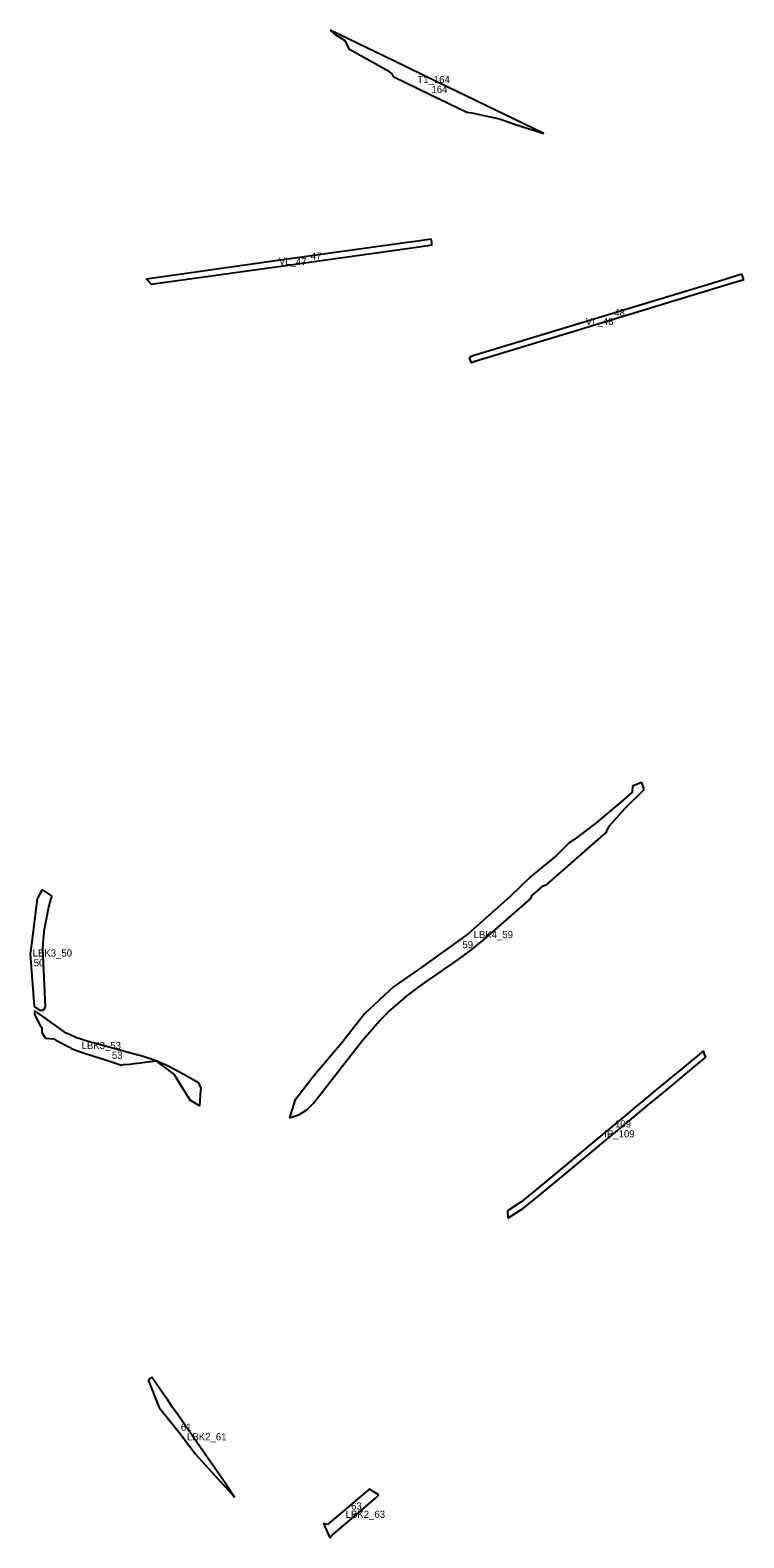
# Model space of a CAD drawing. Extents: x -521939 to -518034, y -1194984 to -1189555.
# Drawn here: x -519031 to -518034, y -1194984 to -1192880 of the extents above; entities that cross this region are included whole.
import ezdxf

# ---------------------------------------------------------------- set-up
doc = ezdxf.new("R2010")
doc.units = 0
for name, color, linetype in [('96120023', 7, 'Continuous'), ('96140023', 7, 'Continuous'), ('ID VPO', 7, 'Continuous'), ('ID VPS', 7, 'Continuous')]:
    doc.layers.add(name, color=color, linetype=linetype)

msp = doc.modelspace()

# ---------------------------------------------------------------- linework, layer by layer
at = {"layer": '96120023'}
for points in [[(-518313.58, -1193023.8), (-518462.75, -1192951.72), (-518523.11, -1192922.54), (-518611.93, -1192879.62), (-518611.95, -1192879.61)], [(-518611.95, -1192879.61), (-518604.74, -1192885.62)], [(-518604.74, -1192885.62), (-518591.47, -1192894.23)], [(-518591.47, -1192894.23), (-518586.01, -1192905.56), (-518533.4, -1192935.15)], [(-518533.4, -1192935.15), (-518525.77, -1192940.63), (-518522.92, -1192944.85)], [(-518522.92, -1192944.85), (-518472.09, -1192969.41)], [(-518472.09, -1192969.41), (-518421.27, -1192993.97)], [(-518421.27, -1192993.97), (-518421.26, -1192993.97)], [(-518421.26, -1192993.97), (-518414.09, -1192994.92), (-518388.43, -1193000.81), (-518375.31, -1193003.18), (-518354.48, -1193010.65)], [(-518354.48, -1193010.65), (-518345.74, -1193013.45)], [(-518345.74, -1193013.45), (-518332.79, -1193017.61), (-518313.58, -1193023.8)], [(-518471.02, -1193171.35), (-518489.33, -1193173.91)], [(-518469.31, -1193179.19), (-518471.02, -1193171.35)], [(-518489.33, -1193173.91), (-518507.69, -1193176.48), (-518688.29, -1193201.76), (-518868.39, -1193226.97), (-518861.71, -1193234.11), (-518680.88, -1193208.8), (-518488.19, -1193181.83)], [(-518488.19, -1193181.83), (-518469.31, -1193179.19)], [(-518037.03, -1193220.36), (-518069.91, -1193230.34), (-518241.69, -1193282.48), (-518414.03, -1193334.79)], [(-518411.17, -1193342.06), (-518236.07, -1193288.88), (-518060.97, -1193235.7), (-518034.3, -1193227.6)], [(-518034.3, -1193227.6), (-518037.03, -1193220.36)], [(-518414.03, -1193334.79), (-518417.99, -1193336.8)], [(-518417.99, -1193336.8), (-518415.16, -1193344.07)], [(-518415.16, -1193344.07), (-518411.17, -1193342.06)], [(-518090.78, -1194303.93), (-518120.84, -1194329.01)], [(-518087.28, -1194312.72), (-518089.43, -1194308.57), (-518090.78, -1194303.93)], [(-518120.84, -1194329.01), (-518156.04, -1194358.17)], [(-518152.05, -1194366.76), (-518087.28, -1194312.72)], [(-518173.76, -1194372.91), (-518185.81, -1194382.9)], [(-518156.04, -1194358.17), (-518173.76, -1194372.91)], [(-518168.73, -1194380.59), (-518153.38, -1194367.87), (-518152.05, -1194366.76)], [(-518185.81, -1194382.9), (-518199.57, -1194394.33)], [(-518185.85, -1194394.67), (-518168.73, -1194380.59)], [(-518274.04, -1194467.87), (-518229.68, -1194431.04), (-518207.82, -1194412.86), (-518185.85, -1194394.67)], [(-518199.57, -1194394.33), (-518245.06, -1194432.12)], [(-518245.06, -1194432.12), (-518304.03, -1194481.14)], [(-518293.63, -1194484.18), (-518274.04, -1194467.87)], [(-518317.05, -1194491.98), (-518340.81, -1194511.5)], [(-518319.41, -1194505.51), (-518293.63, -1194484.18)], [(-518304.03, -1194481.14), (-518317.05, -1194491.98)], [(-518340.81, -1194511.5), (-518345.29, -1194514.98), (-518364.14, -1194527.29)], [(-518363.86, -1194537.39), (-518341.98, -1194523.73), (-518319.41, -1194505.51)], [(-518364.14, -1194527.29), (-518363.86, -1194537.39)]]:
    msp.add_lwpolyline(points, dxfattribs=at)
at = {"layer": '96140023'}
for points in [[(-518176.81, -1193929.72), (-518179.54, -1193930.3), (-518189.98, -1193934.67)], [(-518173.64, -1193939.33), (-518176.81, -1193929.72)], [(-518225.95, -1193998.27), (-518222.25, -1193990.41), (-518200, -1193965.24), (-518173.64, -1193939.33)], [(-518190.04, -1193942.98), (-518205.7, -1193956.46)], [(-518189.98, -1193934.67), (-518190.04, -1193942.98)], [(-518205.7, -1193956.46), (-518240.91, -1193986.11)], [(-518240.91, -1193986.11), (-518271.56, -1194009.45), (-518278.37, -1194013.9)], [(-518655.68, -1194393.54), (-518644.23, -1194386.38), (-518634.76, -1194376.7), (-518566.27, -1194288.86), (-518542.85, -1194262.27), (-518530.28, -1194249.78), (-518503.56, -1194226.5), (-518482.17, -1194210.72), (-518433.41, -1194176.9), (-518415.71, -1194163.89), (-518398.75, -1194149.91), (-518332.7, -1194092.34), (-518329.88, -1194087.32), (-518314.52, -1194073.94), (-518309.55, -1194072.16), (-518226.78, -1194000.03)], [(-518278.37, -1194013.9), (-518296.03, -1194031.57), (-518332.33, -1194061.21)], [(-518226.78, -1194000.03), (-518225.95, -1193998.27)], [(-518332.33, -1194061.21), (-518361.02, -1194088.99), (-518419.1, -1194140.67), (-518483.93, -1194187.46), (-518523.23, -1194214.71)], [(-519020.73, -1194091.88), (-519024.61, -1194121.8), (-519028.49, -1194151.72), (-519029.89, -1194162.52), (-519030.29, -1194165.62), (-519030.69, -1194168.71), (-519027.95, -1194205.37), (-519025.2, -1194242.02)], [(-519013.71, -1194079.07), (-519020.73, -1194091.88)], [(-518999.95, -1194088.17), (-519013.71, -1194079.07)], [(-519004.84, -1194105.44), (-519001.62, -1194092.79), (-518999.95, -1194088.17)], [(-519012.79, -1194161.44), (-519012.2, -1194148.13), (-519010.43, -1194134.4), (-519004.84, -1194105.44)], [(-519012.22, -1194247.18), (-519009.11, -1194242.54), (-519012.79, -1194161.44)], [(-518523.23, -1194214.71), (-518563.39, -1194252.1)], [(-519025.2, -1194242.02), (-519017.78, -1194247.27)], [(-518793.68, -1194380.64), (-518792.24, -1194359.26), (-518791.99, -1194355.76), (-518795.83, -1194348.62), (-518799.64, -1194346.49), (-518816.36, -1194337.16), (-518838.06, -1194325.4), (-518851.56, -1194319.21), (-518862.69, -1194315.05), (-518865.77, -1194314.1), (-518872.91, -1194311.92), (-518892.05, -1194306.64), (-518905.25, -1194303.03), (-518910.54, -1194301.58), (-518937.1, -1194294.31), (-518946.44, -1194291.75), (-518954.36, -1194289.64), (-518962.17, -1194287.03), (-518966.08, -1194285.71), (-518975.52, -1194281.45), (-518980.26, -1194279.31), (-518993.95, -1194269.72), (-519001.41, -1194264.41), (-519008.87, -1194259.09), (-519017.53, -1194252.96), (-519023.94, -1194248.41), (-519024.71, -1194250.04), (-519024.49, -1194253.08)], [(-519024.49, -1194253.08), (-519017.06, -1194268.42)], [(-519017.78, -1194247.27), (-519012.22, -1194247.18)], [(-518563.39, -1194252.1), (-518595.65, -1194293.01), (-518634.33, -1194338.71), (-518661.16, -1194373.51)], [(-519017.06, -1194268.42), (-519014.59, -1194271.5)], [(-519014.59, -1194271.5), (-519014.52, -1194278.4), (-519009.2, -1194286.28)], [(-519009.2, -1194286.28), (-518997.55, -1194287.28), (-518994.7, -1194289.4), (-518975.86, -1194299.17)], [(-518975.86, -1194299.17), (-518972.84, -1194300.73)], [(-518972.84, -1194300.73), (-518969.65, -1194302.39), (-518959.1, -1194305.82)], [(-518959.1, -1194305.82), (-518939.19, -1194312.3)], [(-518939.19, -1194312.3), (-518928.2, -1194315.87)], [(-518928.2, -1194315.87), (-518903.28, -1194323.98)], [(-518903.28, -1194323.98), (-518901.43, -1194323.75)], [(-518901.43, -1194323.75), (-518900.67, -1194323.31), (-518891.75, -1194322.51), (-518855.36, -1194317.86)], [(-518855.36, -1194317.86), (-518829.53, -1194336.97)], [(-518829.53, -1194336.97), (-518816.88, -1194357.57), (-518807.62, -1194372.64)], [(-518807.62, -1194372.64), (-518794.51, -1194380.48)], [(-518794.51, -1194380.48), (-518793.68, -1194380.64)], [(-518661.16, -1194373.51), (-518668.49, -1194397.81)], [(-518668.49, -1194397.81), (-518655.68, -1194393.54)], [(-518860.9, -1194759.36), (-518865.86, -1194763.22)], [(-518865.86, -1194763.22), (-518855.5, -1194789.32)], [(-518845.5, -1194781.65), (-518860.9, -1194759.36)], [(-518855.5, -1194789.32), (-518850.84, -1194801.06)], [(-518838.55, -1194791.71), (-518845.5, -1194781.65)], [(-518831.36, -1194802.11), (-518838.55, -1194791.71)], [(-518850.84, -1194801.06), (-518850.19, -1194802.69)], [(-518850.19, -1194802.69), (-518843.34, -1194811.13)], [(-518843.34, -1194811.13), (-518835.53, -1194820.44)], [(-518824.2, -1194812.48), (-518831.36, -1194802.11)], [(-518745.52, -1194926.78), (-518758.18, -1194908.03), (-518809.54, -1194833.7), (-518824.2, -1194812.48)], [(-518835.53, -1194820.44), (-518820.29, -1194839.32)], [(-518820.29, -1194839.32), (-518800.02, -1194866.93), (-518745.52, -1194926.78)], [(-518561.44, -1194919.5), (-518588.48, -1194942.32), (-518615.53, -1194965.15)], [(-518557.27, -1194915.81), (-518559.35, -1194917.65), (-518561.44, -1194919.5)], [(-518543.87, -1194923.75), (-518557.27, -1194915.81)], [(-518578.49, -1194954.01), (-518547.93, -1194927.89)], [(-518547.93, -1194927.89), (-518543.87, -1194923.75)], [(-518609.05, -1194980.13), (-518578.49, -1194954.01)], [(-518615.53, -1194965.15), (-518621.14, -1194963.55)], [(-518621.14, -1194963.55), (-518612.46, -1194983.75)], [(-518612.46, -1194983.75), (-518609.05, -1194980.13)]]:
    msp.add_lwpolyline(points, dxfattribs=at)

# ---------------------------------------------------------------- texts
at = {"layer": '96120023'}
for s, rotation, p in [('T1_164', 0, (-518490.18, -1192953.48)), ('VL_47', 0, (-518683.34, -1193207.28)), ('VL_48', 360, (-518255.01, -1193291.13)), ('IP_109', 360, (-518229.22, -1194424.87))]:
    msp.add_text(s, height=10, rotation=rotation, dxfattribs=at).set_placement(p)
at = {"layer": '96140023'}
for s, rotation, p in [('LBK4_59', 0, (-518411.62, -1194146.8)), ('LBK3_50', 0, (-519027.22, -1194172.56)), ('LBK3_53', 0, (-518958.9, -1194301.56)), ('LBK2_61', 360, (-518811.67, -1194847.67)), ('LBK2_63', 360, (-518590.25, -1194955.87))]:
    msp.add_text(s, height=10, rotation=rotation, dxfattribs=at).set_placement(p)
at = {"layer": 'ID VPO'}
for s, rotation, p in [('59', 360, (-518427.14, -1194160.76)), ('53', 0, (-518916.57, -1194315.23)), ('61', 360, (-518820.22, -1194834.18)), ('63', 360, (-518582.56, -1194944.29))]:
    msp.add_text(s, height=10, rotation=rotation, dxfattribs=at).set_placement(p)
msp.add_text('50', height=10, dxfattribs=at).set_placement((-519025.78, -1194186.16))
at = {"layer": 'ID VPS'}
for s, rotation, p in [('164', 0, (-518470.46, -1192967.25)), ('47', 360, (-518638.92, -1193200.08)), ('48', 360, (-518215.21, -1193278.8)), ('109', 0, (-518214.18, -1194410.95))]:
    msp.add_text(s, height=10, rotation=rotation, dxfattribs=at).set_placement(p)

doc.saveas('drawing.dxf')
